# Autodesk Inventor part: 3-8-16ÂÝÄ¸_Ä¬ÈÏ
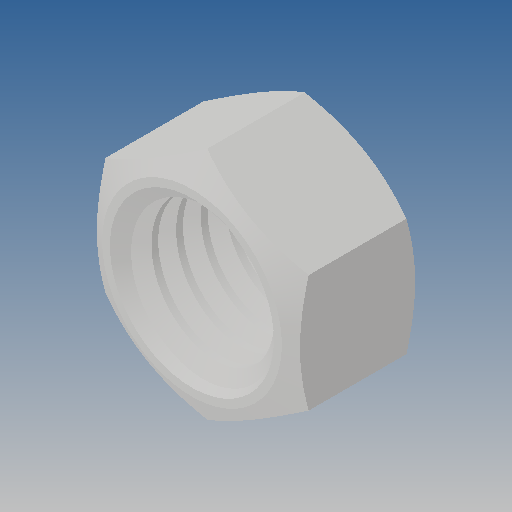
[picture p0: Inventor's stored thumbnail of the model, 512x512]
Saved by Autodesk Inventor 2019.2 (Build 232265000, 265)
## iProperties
Created: 2010-06
Part Number: 3-8-16ÂÝÄ¸_Ä¬ÈÏ
Material: Ogólny
Document SubType Name: Modeling
Designer: CADENGINEERING4
Density: 1 g/cm^3
Appearance: Domyślna
Author: CADENGINEERING4
Revision Number: ÈÎºÎ
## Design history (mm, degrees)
feature "NONE"
node "Bryła1"
